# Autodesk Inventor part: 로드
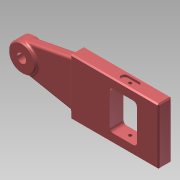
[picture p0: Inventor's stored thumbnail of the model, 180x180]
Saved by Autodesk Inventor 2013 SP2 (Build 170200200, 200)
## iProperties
Created: 2025-04
Part Number: 로드
Material: Generic
Document SubType Name: Modeling
Designer: i
Density: 1 g/cm^3
Author: i
변환 표준: STEP AP214IS
전처리기: Build: 200, Release: 2013 SP2 Update 6 - Date: Thu 07/17/2014
전송 단위: 밀리미터
불확실성: 0.01
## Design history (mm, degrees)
node "로드1"
node "솔리드1"
node "기준1"
